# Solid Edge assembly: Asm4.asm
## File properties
Author: Robert a Rhodes jr
Template: normal.asm
Last saved by: Robert a Rhodes jr
Revision: 1
Application: Solid Edge
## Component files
main assem.asm
arti subassm.asm
link pin.par
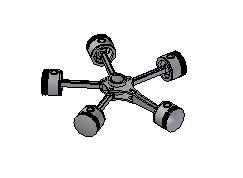
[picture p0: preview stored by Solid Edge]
